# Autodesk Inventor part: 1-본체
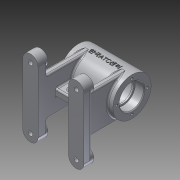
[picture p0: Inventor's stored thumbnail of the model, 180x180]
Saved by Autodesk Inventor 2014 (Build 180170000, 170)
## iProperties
Created: 2015-11
Part Number: 1-본체
Material: 알루미늄 6061
Document SubType Name: Modeling
Designer: test_26
Density: 2.71 g/cm^3
Appearance: 알루미늄 - 평지
Mass: 359.022 g
Surface Area: 460.934 cm^2
Volume: 132.481 cm^3
Author: test_26
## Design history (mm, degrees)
sketch "스케치1"
  geometry: L1 (35, 0)-(-35, 0); L2 (-35, 0)-(-35, 25); L3 (-35, 25)-(35, 25); L4 (35, 25)-(35, 0); L5 (-35, 16)-(-23, 16); L6 (-23, 16)-(-23, 14); L7 (-23, 14)-(-21, 14); L8 (-21, 14)-(-21, 21); L9 (-21, 21)-(21, 21); L10 (21, 21)-(21, 14); L11 (21, 14)-(23, 14); L12 (23, 14)-(23, 16); L13 (23, 16)-(35, 16); 2 further points
  constraints: 26 end point, 8 parallel, 4 perpendicular, 2 point on line, 1 coincident, 1 horizontal, 1 midpoint
  dimensions: "d0" = 50 diameter of L3 L1; "d1" = 28 diameter of L7 L1; "d2" = 32 diameter of L5 L1; "d3" = 32 diameter of L13 L1; "d4" = 42 diameter of L9 L1; "d5" = 28 diameter of L11 L1; "d6" = 12 distance of L5.start L5.end; "d7" = 70 distance between parallel lines of L4 L2; "d8" = 42 distance of L8.end L9.end; "d9" = 12 distance of L12.end L13.end; "d10" = 2 distance of L6.end L7.end
revolve "회전1" sketch "스케치1" stored, may be unused: angle "d11" = 90 deg
node "작업 평면1"
sketch "스케치2"
  geometry: L1 (-30, -40)-(-30, 40); L2 (-20, -40)-(-20, 40); L3 (-40, 40)-(-40, -40); L4 (30, -40)-(30, 40); L5 (20, -40)-(20, 40); L6 (40, 40)-(40, -40); C1 r 10 at (-30, 40); C2 r 10 at (30, 40); C3 r 10 at (-30, -40); C4 r 10 at (30, -40); A1 r 10 centre (-30, -40) between (-40, -40) and (-20, -40); A2 r 10 centre (-30, 40) between (-20, 40) and (-40, 40); A3 r 10 centre (30, -40) between (20, -40) and (40, -40); A4 r 10 centre (30, 40) between (40, 40) and (20, 40); 3 further points
  constraints: 16 end point, 8 centre point, 8 point on circle, 8 tangent, 4 coincident, 3 parallel, 2 concentric, 2 horizontal alignment, 2 midpoint, 1 vertical
  dimensions: "d13" = 20 distance between parallel lines of L2 L3; "d14" = 80 distance of L1.start L1.end; "d15" = 80 distance of L4.start L4.end; "d16" = 80 distance between parallel lines of L6 L3; "d18" = 40 distance from line of point (0, 0) L3; "d19" = 20 distance between parallel lines of L6 L5; "d20" = 20 diameter of C1; "d21" = 20 diameter of C2
extrude "돌출1" join sketch "스케치2" distance "d22" = 10; taper "d23" = 0 deg
extrude "돌출2" join sketch "스케치2" distance "d24" = 13; taper "d25" = 0 deg
sketch "스케치3"
  geometry: L1 (-20, -40)-(-20, 40) reference; L2 (-20, 25)-(-28, 25); L3 (-28, 25)-(-28, -25); L4 (-28, -25)-(-20, -25); L5 (-20, -25)-(-20, 25); L6 (20, 25)-(28, 25); L7 (28, 25)-(28, -25); L8 (28, -25)-(20, -25); L9 (20, -25)-(20, 25); L10 (20, 40)-(20, -40) reference; 3 further points
  constraints: 16 end point, 4 parallel, 2 horizontal, 2 horizontal alignment, 2 midpoint, 2 perpendicular, 1 collinear, 1 point on line
  dimensions: "d26" = 50 distance between parallel lines of L4 L2; "d27" = 50 distance between parallel lines of L8 L6; "d28" = 8 distance between parallel lines of L1 L3; "d30" = 8 distance between parallel lines of L7 L9
extrude "돌출3" join sketch "스케치3" stored distance "d31" = 13; taper "d32" = 0 deg
node "작업 평면2"
sketch "스케치4"
  geometry: L1 (20, -4)-(-20, -4); L2 (-20, -4)-(-20, 4); L3 (-20, 4)-(20, 4); L4 (20, 4)-(20, -4); L5 (20, -4)-(-20, 4); L6 (-20, -4)-(20, 4); L7 (-20, -40)-(-20, 40) reference; L8 (20, -40)-(20, 40) reference; 1 further point
  constraints: 12 end point, 2 midpoint, 2 parallel, 1 collinear, 1 horizontal, 1 perpendicular
  dimensions: "d34" = 8 distance between parallel lines of L1 L3
extrude "돌출4" join sketch "스케치4" stored distance "d35" = 13; taper "d36" = 0 deg
sketch "스케치5"
  geometry: L1 (0, 20.322)-(40, 20.322) reference; L2 (28, 10)-(12, 10); L3 (28, 13.5)-(12, 13.5); L4 (12, 6.5)-(28, 6.5); L5 (40, -23)-(60, -23) reference; A1 r 3.5 centre (28, 10) between (28, 6.5) and (28, 13.5); A2 r 3.5 centre (12, 10) between (12, 13.5) and (12, 6.5); 2 further points
  constraints: 8 end point, 4 point on circle, 4 tangent, 2 centre point, 2 parallel, 1 midpoint, 1 vertical alignment
  dimensions: "d37" = 33 distance from line of L5 point (20, 10); "d38" = 23 dimension on A1 A2; "d39" = 3.5 radius of A2
extrude "돌출5" cut sketch "스케치5" stored distance "d40" = 13; taper "d41" = 0 deg
sketch "스케치6"
  geometry: C1 r 10 at (0, 0) reference; C2 r 6 at (0, 0); 1 further point
  constraints: 1 centre point, 1 coincident
  dimensions: "d42" = 12 diameter of C2
extrude "돌출6" cut sketch "스케치6" distance "d43" = 4; taper "d44" = 0 deg
sketch "스케치7"
  geometry: C1 r 3 at (-30, -40); A1 r 10 centre (-30, -40) between (-40, -40) and (-20, -40) reference; 1 further point
  constraints: 1 centre point, 1 coincident
  dimensions: "d45" = 6 diameter of C1
extrude "돌출7" cut sketch "스케치7" stored distance "d46" = 4; taper "d47" = 0 deg
sketch "스케치9"
  geometry: C1 r 16 at (0, 0) reference; 1 further point
  constraints: 1 vertical alignment
  dimensions: "d48" = 20 distance of point (0, 20) C1.centre
hole "구멍1" sketch "스케치9" at (0, 20) diameter "d49" = 3.242; stored, may be unused: countersink angle "d53" = 90 deg, drill point angle "d55" = 118 deg; dims "d50" = 8, "d51" = 4, "d52" = 2, "d54" = 10
node "작업 평면3"
sketch "스케치10"
  geometry: C1 r 5 at (0, 0); 1 further point
  constraints: 1 centre point, 1 coincident
  dimensions: "d60" = 10 diameter of C1
extrude "돌출8" join sketch "스케치10" stored distance "d61" = 4; taper "d62" = 0 deg
sketch "스케치11"
  geometry: C1 r 5 at (0, 0) reference; 1 further point
  constraints: 1 coincident
hole "구멍2" sketch "스케치11" at (0, 0) diameter "d63" = 5.188; stored, may be unused: countersink angle "d67" = 90 deg, drill point angle "d69" = 118 deg; dims "d64" = 8, "d65" = 4, "d66" = 2, "d68" = 10
sketch "스케치12"
  geometry: L1 (0, 0)-(-24.249, -14); L2 (0, 0)-(-31.998, 0)
  constraints: 4 end point, 1 horizontal
  dimensions: "d70" = 30 deg angle of L2 L1; "d71" = 28 distance of L1.start L1.end
node "작업 평면4"
sketch "스케치13"
  geometry: C1 r 6 at (0, 0); 1 further point
  constraints: 1 centre point, 1 coincident
  dimensions: "d72" = 12 diameter of C1
extrude "돌출9" join sketch "스케치13" stored distance "d73" = 4; taper "d74" = 0 deg
sketch "스케치14"
  geometry: C1 r 6 at (0, 0) reference; 1 further point
  constraints: 1 coincident
hole "구멍3" sketch "스케치14" at (0, 0) diameter "d75" = 5.188; stored, may be unused: countersink angle "d79" = 90 deg, drill point angle "d81" = 118 deg; dims "d76" = 10, "d77" = 4, "d78" = 2, "d80" = 10
node "작업 평면5"
sketch "스케치16"
  geometry: L1 (-35, 25)-(35, 25) reference; L2 (35, -25)-(35, 25) reference; 2 further points
  constraints: 1 other
  dimensions: "d83" = 25 distance from line of L1 point (0, 0); "d84" = 35 distance from line of L2 point (0, 0)
feature "엠보싱1" sketch "스케치16" dims "d0" = 50, "d1" = 28, "d2" = 32, "d3" = 32, "d4" = 42, "d5" = 28, "d6" = 12, "d7" = 70, "d8" = 42, "d9" = 12, "d10" = 2, "d13" = 20, "d14" = 80, "d15" = 80, "d16" = 80, "d18" = 40, "d19" = 20, "d20" = 20, "d21" = 20, "d85" = 0.5, "d86" = 0
fillet "모깎기1" dims "d87" = 0.3
fillet "모깎기2" dims "d88" = 3
fillet "모깎기3" dims "d92" = 2
fillet "모깎기4" dims "d93" = 2
fillet "모깎기5" dims "d94" = 2
fillet "모깎기6" dims "d95" = 2
chamfer "모따기2" distance "d96" = 1; stored, may be unused: second distance "d97" = 2, angle "d98" = 45 deg
fillet "모깎기7" dims "d99" = 0.3
node "솔리드1"
mirror "대칭1"
mirror "대칭2"
pattern_circular "원형 패턴1" dims angle "d57" = 360 deg
mirror "대칭3"
other parameters: "d12" = -68, "d33" = -45, "d59" = 28, "d82" = 25.5
